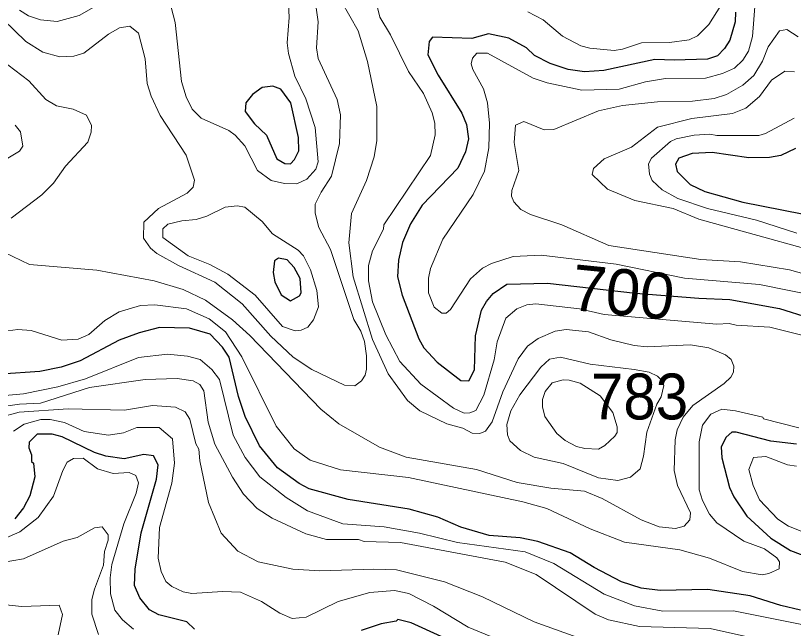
# Model space of a CAD drawing. Extents: x 673.3 to 698.5, y 6984.3 to 7012.3.
# Drawn here: x 679.596 to 680.952, y 6991.869 to 6992.938 of the extents above; entities that cross this region are included whole.
import ezdxf
from ezdxf.enums import TextEntityAlignment as Align

# ---------------------------------------------------------------- set-up
doc = ezdxf.new("R2010")
doc.units = 0
doc.header["$LTSCALE"] = 0.032
doc.layers.add('1', color=7, linetype='Continuous', lineweight=25)
doc.layers.add('2', color=7, linetype='Continuous', lineweight=13)
doc.layers.add('21', color=7, linetype='Continuous')
doc.layers.add('61', color=7, linetype='Continuous')

msp = doc.modelspace()

# ---------------------------------------------------------------- linework, layer by layer
at = {"layer": '1'}
for points in [[(680.8508, 6992.9437), (680.8506, 6992.9267), (680.841, 6992.8947), (680.8321, 6992.8802), (680.8197, 6992.8676), (680.8025, 6992.8613), (680.7439, 6992.8595), (680.7103, 6992.861), (680.6216, 6992.8419), (680.588, 6992.8392), (680.5594, 6992.8434), (680.5282, 6992.8537), (680.501, 6992.868), (680.4866, 6992.8814), (680.456, 6992.8984), (680.4205, 6992.9057), (680.3916, 6992.8978), (680.3227, 6992.8998), (680.3172, 6992.8925), (680.315, 6992.869), (680.3328, 6992.8337), (680.3738, 6992.7675), (680.3825, 6992.7475), (680.3856, 6992.7226), (680.3806, 6992.7), (680.3671, 6992.6716), (680.305, 6992.6069), (680.2844, 6992.5746), (680.2707, 6992.5419), (680.2635, 6992.5114), (680.2619, 6992.482), (680.2699, 6992.4501), (680.2991, 6992.3739), (680.3076, 6992.3581), (680.3312, 6992.3331), (680.3722, 6992.3016), (680.3864, 6992.3009), (680.3962, 6992.3199), (680.3978, 6992.3794), (680.4086, 6992.424), (680.4172, 6992.4392), (680.4287, 6992.4529), (680.4527, 6992.469), (680.5236, 6992.4709), (680.6768, 6992.4533), (680.7871, 6992.445), (680.8412, 6992.4424), (680.9279, 6992.4269), (680.9796, 6992.4107)], [(680.9555, 6992.7056), (680.9301, 6992.6937), (680.9106, 6992.69), (680.8745, 6992.6894), (680.8102, 6992.699), (680.7757, 6992.6973), (680.7523, 6992.6891), (680.7465, 6992.6782), (680.7491, 6992.6659), (680.7723, 6992.643), (680.7976, 6992.6309), (680.864, 6992.6121), (680.9672, 6992.5917)], [(680.9644, 6991.901), (680.9302, 6991.9091), (680.8764, 6991.9262), (680.803, 6991.9368), (680.7196, 6991.9352), (680.6864, 6991.9392), (680.6522, 6991.9504), (680.6049, 6991.9752), (680.5627, 6992.0009), (680.5068, 6992.0209), (680.4757, 6992.0272), (680.4217, 6992.0309), (680.3726, 6992.0456), (680.3324, 6992.063), (680.282, 6992.0773), (680.176, 6992.094), (680.1082, 6992.1125), (680.0903, 6992.1216), (680.0528, 6992.149), (680.0216, 6992.1875), (679.9962, 6992.2388), (679.9851, 6992.2736), (679.9688, 6992.342), (679.9572, 6992.3592), (679.9353, 6992.3822), (679.8995, 6992.3927), (679.8473, 6992.3936), (679.8118, 6992.3847), (679.777, 6992.3715), (679.7086, 6992.3355), (679.676, 6992.3246), (679.6386, 6992.317), (679.5707, 6992.3122)], [(679.9084, 6991.8676), (679.895, 6991.8806), (679.8461, 6991.8927), (679.8299, 6991.9014), (679.813, 6991.9224), (679.8034, 6991.9441), (679.805, 6991.9722), (679.8149, 6992.0359), (679.842, 6992.1296), (679.8448, 6992.1541), (679.8368, 6992.1701), (679.8199, 6992.1721), (679.7857, 6992.1648), (679.7535, 6992.1692), (679.7336, 6992.176), (679.6776, 6992.2031), (679.66, 6992.2079), (679.6342, 6992.2079), (679.62, 6992.1939), (679.6194, 6992.1841), (679.6242, 6992.1718), (679.6243, 6992.1601), (679.6274, 6992.1571), (679.6298, 6992.1332), (679.621, 6992.1003), (679.6099, 6992.0794), (679.595, 6992.0599)], [(680.9571, 6992.1901), (680.9129, 6992.1954), (680.8523, 6992.2112), (680.8444, 6992.2112), (680.8346, 6992.2024), (680.8263, 6992.1856), (680.8273, 6992.1667), (680.8407, 6992.115), (680.8481, 6992.0983), (680.8708, 6992.0648), (680.9125, 6992.0264), (680.9472, 6992.0051), (681.0172, 6991.978)], [(680.338, 6991.855), (680.2858, 6991.8788), (680.2623, 6991.8845), (680.2596, 6991.882), (680.2336, 6991.8774), (680.1988, 6991.8658)]]:
    msp.add_lwpolyline(points, dxfattribs=at)
for points in [[(680.0762, 6992.7853), (680.0584, 6992.8092), (680.0445, 6992.8146), (680.0263, 6992.812), (680.0094, 6992.7999), (679.9975, 6992.7854), (679.9963, 6992.7702), (680.0125, 6992.7489), (680.0339, 6992.7289), (680.0518, 6992.6877), (680.0656, 6992.6798), (680.0756, 6992.6789), (680.0824, 6992.6865), (680.0901, 6992.7019), (680.0893, 6992.7247)], [(680.0922, 6992.4794), (680.0818, 6992.4986), (680.0697, 6992.5115), (680.0543, 6992.5148), (680.0473, 6992.5102), (680.0453, 6992.4899), (680.0483, 6992.4735), (680.0591, 6992.4507), (680.0756, 6992.4403), (680.0914, 6992.4489), (680.094, 6992.454)]]:
    msp.add_lwpolyline(points, close=True, dxfattribs=at)
at = {"layer": '2'}
for points in [[(680.7288, 6992.8277), (680.7985, 6992.8285), (680.8283, 6992.8365), (680.8495, 6992.846), (680.8638, 6992.8595), (680.8738, 6992.8756), (680.8808, 6992.9012), (680.8891, 6993.0059)], [(679.8612, 6992.9773), (679.8743, 6992.9252), (679.8852, 6992.8228), (679.8935, 6992.7957), (679.904, 6992.7745), (679.9196, 6992.7589), (679.9679, 6992.7372), (679.9791, 6992.7293), (679.9961, 6992.7107), (680.0181, 6992.6674), (680.0416, 6992.6501), (680.065, 6992.6445), (680.0866, 6992.6444), (680.1041, 6992.6522), (680.1195, 6992.6695), (680.1234, 6992.6827), (680.1186, 6992.7426), (680.1021, 6992.7921), (680.083, 6992.8316), (680.0721, 6992.8716), (680.0697, 6992.8902), (680.073, 6992.9342), (680.0704, 6992.9938)], [(680.8045, 6992.3582), (680.7728, 6992.3634), (680.697, 6992.3601), (680.6742, 6992.3624), (680.6337, 6992.3725), (680.5946, 6992.3863), (680.5558, 6992.3903), (680.5367, 6992.3871), (680.507, 6992.3745), (680.4883, 6992.361), (680.4721, 6992.3393), (680.4454, 6992.2815), (680.4268, 6992.2293), (680.4152, 6992.2131), (680.4056, 6992.2088), (680.3919, 6992.2094), (680.3757, 6992.218), (680.3481, 6992.2256), (680.3009, 6992.2484), (680.2793, 6992.2666), (680.2457, 6992.313), (680.2181, 6992.3726), (680.1845, 6992.482), (680.1772, 6992.5414), (680.1816, 6992.5926), (680.208, 6992.6499), (680.2212, 6992.6912), (680.226, 6992.7198), (680.226, 6992.7791), (680.2097, 6992.8573), (680.1936, 6992.9108), (680.15, 6992.988)], [(680.1126, 6992.3204), (680.1693, 6992.2932), (680.1877, 6992.2918), (680.1991, 6992.3007), (680.2057, 6992.3108), (680.2081, 6992.3212), (680.2081, 6992.3445), (680.2047, 6992.3693), (680.1978, 6992.3874), (680.1861, 6992.4077), (680.1454, 6992.5296), (680.1248, 6992.5681), (680.1186, 6992.5929), (680.1187, 6992.6087), (680.1287, 6992.6296), (680.1467, 6992.6577), (680.1608, 6992.7147), (680.1625, 6992.7644), (680.1568, 6992.791), (680.1236, 6992.8628), (680.121, 6992.8813), (680.1234, 6992.9265), (680.1177, 6992.9677)], [(680.2245, 6992.9607), (680.2311, 6992.9349), (680.2496, 6992.9042), (680.281, 6992.84), (680.3073, 6992.8019), (680.3225, 6992.768), (680.327, 6992.7498), (680.3278, 6992.7299), (680.3193, 6992.6935), (680.2383, 6992.5726), (680.2373, 6992.5652), (680.2182, 6992.5274), (680.2114, 6992.5019), (680.2112, 6992.4753), (680.2185, 6992.4385), (680.2418, 6992.3808), (680.2658, 6992.3344), (680.3025, 6992.2951), (680.3594, 6992.2532), (680.3784, 6992.2446), (680.3883, 6992.2447), (680.3985, 6992.2488), (680.4125, 6992.2755), (680.4304, 6992.3371), (680.4359, 6992.3688), (680.4508, 6992.4098), (680.4698, 6992.4263), (680.4875, 6992.4335), (680.5031, 6992.4351), (680.5793, 6992.426), (680.6223, 6992.4164), (680.8188, 6992.3993), (680.8398, 6992.4009), (680.8524, 6992.3977), (680.9109, 6992.3944), (680.9759, 6992.3782)], [(680.8322, 6992.9667), (680.8047, 6992.922), (680.785, 6992.9021)], [(679.6033, 6992.9468), (679.6186, 6992.937), (679.6399, 6992.9301), (679.6685, 6992.9271), (679.7071, 6992.9374), (679.7366, 6992.9547)], [(680.785, 6992.9021), (680.7705, 6992.8952), (680.7361, 6992.8904), (680.6875, 6992.8902), (680.6543, 6992.8791), (680.6394, 6992.8769), (680.5969, 6992.8805), (680.5817, 6992.8848), (680.5495, 6992.9016), (680.5158, 6992.9303), (680.4893, 6992.9442)], [(679.5748, 6992.9309), (679.6142, 6992.8922), (679.644, 6992.8739), (679.6736, 6992.8653), (679.6978, 6992.8668), (679.7153, 6992.8721), (679.7581, 6992.9052), (679.7773, 6992.9164), (679.7957, 6992.9188), (679.8105, 6992.9068), (679.822, 6992.8621), (679.8254, 6992.8193), (679.8325, 6992.797), (679.8483, 6992.7635), (679.8935, 6992.6944), (679.9083, 6992.6507), (679.9057, 6992.6385), (679.8951, 6992.628), (679.8453, 6992.6009), (679.8196, 6992.5773), (679.8192, 6992.5493), (679.8314, 6992.5318), (679.8422, 6992.5225), (679.8805, 6992.5017), (679.9435, 6992.4726), (679.991, 6992.4349), (680.0413, 6992.3787), (680.0801, 6992.3422), (680.1126, 6992.3204)], [(681.0781, 6992.457), (680.9453, 6992.4945), (680.8598, 6992.5085), (680.7904, 6992.5125), (680.6302, 6992.5367), (680.5483, 6992.5725), (680.494, 6992.5906), (680.477, 6992.5995), (680.4647, 6992.6126), (680.4606, 6992.6225), (680.4611, 6992.6327), (680.4735, 6992.6677), (680.4655, 6992.7163), (680.4679, 6992.7467), (680.4822, 6992.7527), (680.5174, 6992.7383), (680.5347, 6992.7388), (680.6123, 6992.7712), (680.6539, 6992.7805), (680.7149, 6992.7869), (680.7763, 6992.7884), (680.8138, 6992.7928), (680.8355, 6992.7997), (680.864, 6992.8163), (680.8831, 6992.8333), (680.8984, 6992.858), (680.9078, 6992.8833), (680.9276, 6992.9108), (680.9404, 6992.913), (680.9601, 6992.9006)], [(680.9992, 6992.4473), (680.8927, 6992.4686), (680.7623, 6992.48), (680.6432, 6992.5044), (680.5125, 6992.5198), (680.4633, 6992.5174), (680.4255, 6992.5051), (680.4099, 6992.4973), (680.389, 6992.4783), (680.3542, 6992.4249), (680.3469, 6992.4189), (680.339, 6992.419), (680.3256, 6992.4292), (680.3157, 6992.4544), (680.3157, 6992.4798), (680.3194, 6992.4964), (680.3409, 6992.5475), (680.394, 6992.6256), (680.4133, 6992.6665), (680.4214, 6992.7071), (680.4222, 6992.7502), (680.419, 6992.7856), (680.4117, 6992.8097), (680.3932, 6992.8433), (680.3906, 6992.8534), (680.3928, 6992.8634), (680.4003, 6992.8717), (680.4187, 6992.8717), (680.4986, 6992.8286), (680.5226, 6992.8201), (680.5832, 6992.8073), (680.6484, 6992.809), (680.6943, 6992.8219), (680.7288, 6992.8277)], [(679.5704, 6992.861), (679.6191, 6992.8237), (679.6488, 6992.7911), (679.6676, 6992.7799), (679.6969, 6992.7741), (679.7197, 6992.7637), (679.7289, 6992.7457), (679.7283, 6992.7342), (679.7225, 6992.7171), (679.6832, 6992.6748), (679.6624, 6992.6452), (679.6421, 6992.6249), (679.5887, 6992.5843)], [(680.9539, 6992.8397), (680.9368, 6992.8406), (680.9138, 6992.8249), (680.8928, 6992.7965), (680.8691, 6992.7762), (680.8461, 6992.7667), (680.7751, 6992.7583), (680.7149, 6992.743), (680.6699, 6992.708), (680.6219, 6992.6876), (680.6033, 6992.6707), (680.6011, 6992.6606), (680.6278, 6992.635), (680.6755, 6992.6154), (680.7426, 6992.6014), (680.7874, 6992.5824), (681.0725, 6992.5034)], [(680.9533, 6992.7584), (680.9034, 6992.7318), (680.8917, 6992.7284), (680.8184, 6992.7283), (680.8061, 6992.7307), (680.779, 6992.7291), (680.7474, 6992.7228), (680.738, 6992.7182), (680.7048, 6992.6891), (680.6992, 6992.6791), (680.7014, 6992.661), (680.7057, 6992.6502), (680.7231, 6992.6335), (680.7507, 6992.6186), (680.8021, 6992.6012), (680.8875, 6992.581), (680.9578, 6992.5581)], [(679.5501, 6992.6696), (679.603, 6992.701), (679.6087, 6992.7099), (679.6047, 6992.7351), (679.5955, 6992.7465)], [(679.5771, 6992.5246), (679.6204, 6992.5033), (679.7379, 6992.4938), (679.8379, 6992.475), (679.8884, 6992.4602), (679.9271, 6992.4416), (679.9746, 6992.4071), (680.0048, 6992.3795), (680.1283, 6992.2511), (680.1595, 6992.2257), (680.2308, 6992.1849), (680.2773, 6992.1679), (680.3998, 6992.146), (680.4706, 6992.1238), (680.5291, 6992.1135), (680.5878, 6992.1087), (680.6188, 6992.0959), (680.6868, 6992.0584), (680.7182, 6992.0464), (680.7463, 6992.0436), (680.7613, 6992.0474), (680.7713, 6992.0586), (680.7725, 6992.0705), (680.7502, 6992.1182), (680.7443, 6992.1444), (680.7457, 6992.198), (680.7492, 6992.2153), (680.7599, 6992.2374), (680.7767, 6992.2576), (680.8314, 6992.2961), (680.8431, 6992.3071), (680.8475, 6992.3161), (680.8481, 6992.3263), (680.8435, 6992.338), (680.8337, 6992.3459), (680.8045, 6992.3582)], [(680.9612, 6992.2186), (680.8998, 6992.2348), (680.8985, 6992.2372), (680.8513, 6992.2485), (680.827, 6992.2511), (680.8079, 6992.2425), (680.7935, 6992.2236), (680.7875, 6992.1944), (680.788, 6992.1108), (680.7936, 6992.0922), (680.806, 6992.0684), (680.8185, 6992.0535), (680.8656, 6992.0215), (680.9018, 6992.0076), (680.9231, 6991.9921), (680.9279, 6991.985), (680.9272, 6991.9729), (680.9093, 6991.9648), (680.8976, 6991.9628), (680.8631, 6991.9682), (680.8057, 6991.9916), (680.7543, 6992.006), (680.6577, 6992.0198), (680.598, 6992.0428), (680.5223, 6992.0782), (680.4806, 6992.0899), (680.2813, 6992.132), (680.1628, 6992.1458), (680.1099, 6992.1622), (680.0816, 6992.1821), (680.0503, 6992.2218), (679.9905, 6992.3426), (679.9623, 6992.386), (679.9337, 6992.409), (679.8943, 6992.4262), (679.8391, 6992.4335), (679.8138, 6992.4319), (679.7771, 6992.4211), (679.7518, 6992.4062)], [(679.7518, 6992.4062), (679.724, 6992.3817), (679.7056, 6992.3733), (679.6771, 6992.3717), (679.6235, 6992.3887), (679.6002, 6992.3904), (679.5828, 6992.3881)], [(679.5271, 6992.2704), (679.6102, 6992.278), (679.6701, 6992.2902), (679.718, 6992.3044), (679.8107, 6992.3414), (679.8611, 6992.3472), (679.8962, 6992.3439), (679.9183, 6992.338), (679.9381, 6992.3208), (679.9515, 6992.3032), (679.9758, 6992.2062), (679.9964, 6992.1673), (680.0219, 6992.1336), (680.0678, 6992.0976), (680.1048, 6992.0744), (680.1669, 6992.0515), (680.2389, 6992.0465), (680.3004, 6992.0352), (680.3663, 6992.019), (680.4844, 6992.0025), (680.5347, 6991.9823), (680.6224, 6991.9287), (680.6748, 6991.9087), (680.7246, 6991.8993), (680.8477, 6991.9), (680.9755, 6991.8742)], [(679.5342, 6992.2504), (679.6033, 6992.2601), (679.64, 6992.2621), (679.7252, 6992.2893), (679.8219, 6992.3033), (679.8778, 6992.3049), (679.906, 6992.3007), (679.9175, 6992.2941), (679.9246, 6992.2831), (679.932, 6992.2286), (679.9437, 6992.1902), (679.9741, 6992.1328), (679.9936, 6992.103), (680.0175, 6992.0781), (680.0435, 6992.0611), (680.102, 6992.034), (680.1383, 6992.0239), (680.1938, 6992.0239), (680.2039, 6992.0206), (680.2673, 6992.019), (680.4497, 6991.9848), (680.5035, 6991.9629), (680.6066, 6991.8942), (680.6299, 6991.8841), (680.6835, 6991.8724), (680.8067, 6991.8691), (680.9422, 6991.839)], [(680.5748, 6991.8539), (680.4999, 6991.8808), (680.4103, 6991.9241), (680.3436, 6991.9502), (680.2603, 6991.971), (680.2208, 6991.9726), (680.1265, 6991.9693), (680.0796, 6991.9726), (680.019, 6991.9851), (679.9834, 6992.0037), (679.9545, 6992.035), (679.9328, 6992.0885), (679.9174, 6992.1612), (679.9157, 6992.1816), (679.9107, 6992.1908), (679.8998, 6992.2338), (679.892, 6992.2469), (679.8752, 6992.2548), (679.8351, 6992.2576), (679.7864, 6992.2495), (679.6882, 6992.2519), (679.6027, 6992.2461), (679.5679, 6992.2368)], [(680.4836, 6991.8306), (680.3854, 6991.8712), (680.3249, 6991.9081), (680.2817, 6991.93), (680.2569, 6991.935), (680.2138, 6991.9318), (680.1585, 6991.9163), (680.1027, 6991.8885), (680.0784, 6991.8862), (680.0567, 6991.8956), (680.0252, 6991.9162), (679.9884, 6991.9325), (679.9569, 6991.9335), (679.9032, 6991.9303), (679.8883, 6991.9327), (679.8686, 6991.9425), (679.8584, 6991.9511), (679.8503, 6991.9683), (679.8449, 6991.9918), (679.8474, 6992.0448), (679.8685, 6992.1221), (679.8735, 6992.1571), (679.87, 6992.1997), (679.8466, 6992.2194), (679.8077, 6992.2193), (679.7841, 6992.2104), (679.7584, 6992.2063), (679.7161, 6992.2126), (679.6818, 6992.228), (679.6565, 6992.2332), (679.6403, 6992.2331), (679.6112, 6992.225), (679.5929, 6992.213)], [(679.5617, 6992.0193), (679.6036, 6992.0373), (679.6357, 6992.0627), (679.6626, 6992.0999), (679.6785, 6992.1446), (679.6862, 6992.159), (679.6975, 6992.1656), (679.7139, 6992.1658), (679.7388, 6992.1474), (679.7665, 6992.1395), (679.7945, 6992.1412), (679.8061, 6992.1357), (679.8105, 6992.1231), (679.8067, 6992.1048), (679.785, 6992.0517), (679.7642, 6991.9804), (679.7611, 6991.9573), (679.7617, 6991.9297), (679.7692, 6991.901), (679.7824, 6991.8844), (679.8018, 6991.8678)], [(681.0626, 6992.0005), (680.9433, 6992.0475), (680.925, 6992.0595), (680.8931, 6992.0932), (680.882, 6992.1181), (680.8743, 6992.1464), (680.8824, 6992.1669), (680.9041, 6992.1688), (680.9416, 6992.1542), (680.9575, 6992.1518)], [(679.7411, 6991.8584), (679.7293, 6991.8938), (679.7294, 6991.9194), (679.7337, 6991.9378), (679.7496, 6991.9792), (679.7512, 6992.0032), (679.7577, 6992.023), (679.7577, 6992.0325), (679.7474, 6992.046), (679.7339, 6992.0443), (679.7038, 6992.0278), (679.679, 6992.0212), (679.6102, 6991.9906), (679.5691, 6991.9832)], [(679.4672, 6991.9221), (679.6072, 6991.9075), (679.6722, 6991.9095), (679.6778, 6991.8937), (679.6707, 6991.8577)]]:
    msp.add_lwpolyline(points, dxfattribs=at)
for points in [[(680.0942, 6992.3888), (680.1055, 6992.3944), (680.1158, 6992.407), (680.1244, 6992.4298), (680.1216, 6992.4585), (680.1104, 6992.4943), (680.0983, 6992.5188), (680.0888, 6992.5285), (680.044, 6992.5568), (680.0262, 6992.5788), (679.9959, 6992.6035), (679.9825, 6992.6061), (679.9616, 6992.6037), (679.9299, 6992.588), (679.9112, 6992.5818), (679.886, 6992.5794), (679.8619, 6992.5738), (679.8527, 6992.5656), (679.8532, 6992.5508), (679.897, 6992.5185), (679.9351, 6992.5036), (679.966, 6992.4866), (680.014, 6992.4499), (680.0618, 6992.3957), (680.0833, 6992.3879)], [(680.646, 6992.1273), (680.6681, 6992.1327), (680.685, 6992.1473), (680.691, 6992.1697), (680.6966, 6992.2114), (680.7138, 6992.2598), (680.7217, 6992.2727), (680.7259, 6992.2926), (680.724, 6992.3003), (680.715, 6992.3091), (680.7003, 6992.3159), (680.6744, 6992.3203), (680.5979, 6992.3297), (680.5461, 6992.3422), (680.5268, 6992.3383), (680.5119, 6992.3243), (680.4751, 6992.2761), (680.4592, 6992.2484), (680.4525, 6992.2244), (680.4538, 6992.2065), (680.4579, 6992.1963), (680.4766, 6992.1794), (680.5001, 6992.1679), (680.5505, 6992.1568), (680.612, 6992.1317)], [(680.5396, 6992.2089), (680.519, 6992.2386), (680.5144, 6992.2553), (680.5144, 6992.2681), (680.5194, 6992.2823), (680.5314, 6992.2974), (680.5508, 6992.3023), (680.5613, 6992.3022), (680.5805, 6992.2965), (680.6153, 6992.2746), (680.6375, 6992.2457), (680.6446, 6992.2204), (680.6446, 6992.2107), (680.641, 6992.2044), (680.6235, 6992.1878), (680.612, 6992.1817), (680.5884, 6992.1826), (680.5738, 6992.186), (680.5543, 6992.1967)]]:
    msp.add_lwpolyline(points, close=True, dxfattribs=at)

# ---------------------------------------------------------------- texts
at = {"layer": '21', "width": 0.95}
msp.add_text('783', height=0.08, dxfattribs=at).set_placement((680.599, 6992.2335))
at = {"layer": '61'}
msp.add_text('700', height=0.08, rotation=354.289, dxfattribs=at).set_placement((680.6512, 6992.4156), align=Align.CENTER)

doc.saveas('drawing.dxf')
